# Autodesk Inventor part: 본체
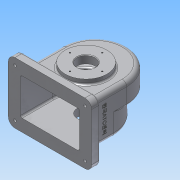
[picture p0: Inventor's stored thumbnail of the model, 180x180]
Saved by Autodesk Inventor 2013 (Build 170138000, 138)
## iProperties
Created: 2017-11
Part Number: 본체
Material: 알루미늄 6061
Document SubType Name: Modeling
Designer: Administrator
Density: 2.71 g/cm^3
Mass: 1079.49 g
Surface Area: 1182.07 cm^2
Volume: 398.335 cm^3
Author: Administrator
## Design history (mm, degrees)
sketch "스케치2"
  geometry: L1 (-58, 0)-(58, 0); L2 (58, 0)-(58, -65); L3 (58, -65)-(-58, -65); L4 (-58, -65)-(-58, 0); L5 (-58, 0)-(58, -65); L6 (58, 0)-(-58, -65); C1 r 58 at (0, 0); 3 further points
  constraints: 12 end point, 3 midpoint, 2 coincident, 2 parallel, 1 centre point, 1 horizontal, 1 perpendicular
  dimensions: "d0" = 116 diameter of C1; "d2" = 65 distance of L1.end L2.end; "d3" = 116 distance of L1.start L1.end
extrude "돌출1" new body sketch "스케치2" stored distance "d4" = 38; taper "d5" = 0 deg
sketch "스케치3"
  geometry: L1 (-58, -65)-(58, -65) reference; L2 (-58, -23)-(58, -23); L3 (58, -23)-(58, -65); L4 (58, -65)-(-58, -65); L5 (-58, -65)-(-58, -23); L6 (-58, -23)-(58, -65); L7 (58, -23)-(-58, -65); A1 r 58 centre (0, -23) between (40, -65) and (-40, -65); 2 further points
  constraints: 12 end point, 5 midpoint, 2 parallel, 2 point on circle, 2 point on line, 1 centre point, 1 horizontal, 1 perpendicular
  dimensions: "d6" = 42 distance of L2.end L3.end; "d8" = 116 distance of L2.start L2.end; "d9" = 116 diameter of A1
extrude "돌출2" join sketch "스케치3" distance "d10" = 38; taper "d11" = 0 deg
feature "쉘1" dims "d12" = 5
sketch "스케치5"
  geometry: L1 (111, -5)-(111, -71) reference; L2 (111, -71)-(5, -71) reference; L3 (5, -71)-(5, -5) reference; L4 (5, -5)-(111, -5) reference; L5 (116, 0)-(116, -76) reference; L6 (0, 0)-(0, -76) reference; L7 (0, -38)-(116, -38); L8 (-17, 17)-(133, 17); L9 (133, 17)-(133, -93); L10 (133, -93)-(-17, -93); L11 (-17, -93)-(-17, 17); L12 (-17, 17)-(133, -93); L13 (133, 17)-(-17, -93); 2 further points
  constraints: 14 end point, 5 midpoint, 2 parallel, 1 horizontal, 1 perpendicular
  dimensions: "d13" = 150 distance of L9.end L10.end; "d15" = 110 distance of L8.end L9.end
extrude "돌출3" join sketch "스케치5" distance "d16" = 15; taper "d17" = 0 deg
sketch "스케치6"
  geometry: L1 (75, -80)-(-75, -80) reference; C1 r 37.5 at (0, -15); 1 further point
  constraints: 1 centre point, 1 midpoint, 1 vertical alignment
  dimensions: "d18" = 75 diameter of C1; "d19" = 65 distance from line of L1 C1.centre
extrude "돌출4" join sketch "스케치6" distance "d20" = 9; taper "d21" = 0 deg
sketch "스케치7"
  geometry: L1 (75, -80)-(-75, -80) reference; C1 r 31 at (0, -15); 2 further points
  constraints: 1 centre point, 1 midpoint, 1 vertical alignment
  dimensions: "d22" = 62 diameter of C1; "d24" = 65 distance from line of L1 C1.centre
extrude "돌출5" join sketch "스케치7" distance "d25" = 10; taper "d26" = 0 deg
sketch "스케치8"
  geometry: C1 r 37.5 at (0, 0) reference; C2 r 16 at (0, 0); 1 further point
  constraints: 1 centre point, 1 coincident
  dimensions: "d27" = 32 diameter of C2
extrude "돌출6" cut sketch "스케치8" stored distance "d28" = 10; taper "d29" = 0 deg
node "작업 평면1"
sketch "스케치9"
  geometry: L1 (0, 0)-(-116, 0) reference; C1 r 6 at (-58, -19); 2 further points
  constraints: 1 centre point, 1 midpoint, 1 vertical alignment
  dimensions: "d31" = 12 diameter of C1; "d32" = 19 distance from line of L1 C1.centre
extrude "돌출7" join sketch "스케치9" stored distance "d33" = 10; taper "d34" = 0 deg
sketch "스케치10"
  geometry: C1 r 6 at (0, 0) reference
hole "구멍1" sketch "스케치10" at (0, 0) diameter "d35" = 4.459; stored, may be unused: countersink angle "d39" = 90 deg, drill point angle "d41" = 118 deg; dims "d36" = 6, "d37" = 4, "d38" = 2, "d40" = 8
sketch "스케치11"
  geometry: C1 r 16 at (0, 0) reference; 2 further points
  constraints: 1 vertical alignment
  dimensions: "d42" = 29 distance of C1.centre point (0, 29)
hole "구멍2" sketch "스케치11" at (0, 29) diameter "d43" = 2.459; stored, may be unused: countersink angle "d47" = 90 deg, drill point angle "d49" = 118 deg; dims "d44" = 6, "d45" = 4, "d46" = 2, "d48" = 8
sketch "스케치12"
  geometry: C1 r 16 at (0, 0) reference; 2 further points
  constraints: 1 vertical alignment
  dimensions: "d53" = 26 distance of C1.centre point (0, 26)
hole "구멍3" sketch "스케치12" at (0, 26) diameter "d54" = 2.459; stored, may be unused: countersink angle "d58" = 90 deg, drill point angle "d60" = 118 deg; dims "d55" = 6, "d56" = 4, "d57" = 2, "d59" = 8
fillet "모깎기1" dims "d64" = 12
sketch "스케치14"
  geometry: A1 r 12 centre (-5, -5) between (-17, -5) and (-5, -17) reference; 1 further point
hole "구멍4" sketch "스케치14" at (-5, -5) diameter "d65" = 5; stored, may be unused: countersink angle "d69" = 90 deg, drill point angle "d71" = 118 deg; dims "d66" = 5, "d67" = 12, "d68" = 5, "d70" = 8
sketch "스케치15"
  geometry: A1 r 12 centre (-5, 81) between (-5, 93) and (-17, 81) reference; A2 r 12 centre (121, 81) between (133, 81) and (121, 93) reference; 1 further point
hole "구멍5" sketch "스케치15" at (-5, 81), (121, 81) diameter "d72" = 5; stored, may be unused: countersink angle "d76" = 90 deg, drill point angle "d78" = 118 deg; dims "d73" = 5, "d74" = 12, "d75" = 5, "d77" = 8
sketch "스케치16"
  geometry: L1 (0, -65)-(0, 0) reference; L2 (81, -80)-(-5, -80) reference; L3 (-5, -65)-(81, -65) reference; 2 further points
  constraints: 1 other
  dimensions: "d79" = 40 distance from line of L2 point (38, -40); "d80" = 38 distance from line of point (38, -40) L1
feature "엠보싱1" sketch "스케치16" dims "d81" = 0.5, "d82" = 0
fillet "모깎기2" dims "d83" = 3
fillet "모깎기3" dims "d84" = 3
fillet "모깎기4" dims "d85" = 8
chamfer "모따기1" distance "d86" = 1; stored, may be unused: second distance "d87" = 2, angle "d88" = 45 deg
fillet "모깎기5" dims "d89" = 3
fillet "모깎기6" dims "d90" = 3
fillet "모깎기7" dims "d91" = 3
node "솔리드1"
pattern_circular "원형 패턴1" dims angle "d51" = 360 deg
pattern_circular "원형 패턴2" dims angle "d62" = 360 deg
mirror "대칭1"
other parameters: "d30" = -144
